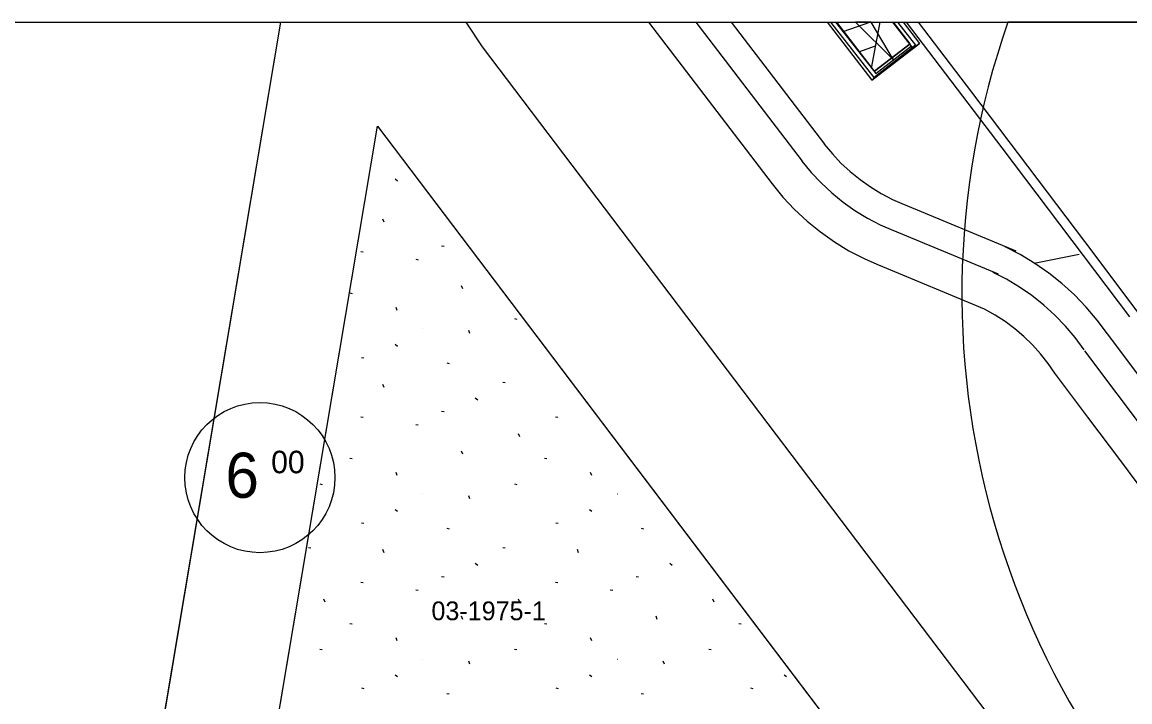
# Model space of a CAD drawing. Extents: x 413946 to 415528, y 4453939 to 4454944.
# Drawn here: x 414350.4 to 414409.5, y 4454907.7 to 4454944 of the extents above; entities that cross this region are included whole.
import ezdxf

# ---------------------------------------------------------------- set-up
doc = ezdxf.new("R2010")
doc.units = 0
for name, color, linetype in [('0_KADASTRO', 7, 'Continuous'), ('0_ÇERÇEVE', 7, 'Continuous'), ('Level 28', 7, 'Continuous'), ('Level 29', 7, 'Continuous'), ('Level 34', 7, 'Continuous'), ('Level 41', 7, 'Continuous'), ('Level 53', 7, 'Continuous'), ('Level 58', 7, 'Continuous'), ('Level 62', 7, 'Continuous'), ('SEMBOL', 7, 'Continuous')]:
    doc.layers.add(name, color=color, linetype=linetype)

msp = doc.modelspace()

# ---------------------------------------------------------------- linework, layer by layer
at = {"layer": '0_KADASTRO'}
for points in [[(414364.196, 4454943.957), (414356.8, 4454900.03), (414337.07, 4454903.37), (414329.44, 4454904.67), (414313.82, 4454907.32), (414291.88, 4454911.04), (414297.69, 4454930.45), (414299.05, 4454935), (414301.17, 4454942.09), (414301.729, 4454943.957)], [(414301.729, 4454943.957), (414364.196, 4454943.957)]]:
    msp.add_lwpolyline(points, dxfattribs=at)
msp.add_lwpolyline([(414362.46, 4454897.43), (414369.36, 4454938.42), (414392.9, 4454907.35), (414404.99, 4454891.41)], close=True, dxfattribs=at)
at = {"layer": '0_ÇERÇEVE'}
msp.add_lwpolyline([(413945.566, 4454943.957), (415494.137, 4454943.957), (415494.137, 4453939.478), (413945.566, 4453939.478)], close=True, dxfattribs=at)
at = {"layer": 'Level 28'}
for p, q in [((414364.196, 4454943.957), (414356.8, 4454900.03)), ((414362.46, 4454897.43), (414369.36, 4454938.42))]:
    msp.add_line(p, q, dxfattribs=at)
at = {"layer": 'Level 29'}
msp.add_line((414369.36, 4454938.42), (414399.16, 4454899.097), dxfattribs=at)
at = {"layer": 'Level 34'}
for points in [[(414364.196, 4454943.957), (414356.8, 4454900.03), (414329.44, 4454904.67), (414313.82, 4454907.32), (414291.88, 4454911.04), (414297.69, 4454930.45), (414301.17, 4454942.09), (414301.729, 4454943.957)], [(414301.729, 4454943.957), (414364.196, 4454943.957)]]:
    msp.add_lwpolyline(points, dxfattribs=at)
at = {"layer": 'Level 41'}
for p, q in [((414370.296, 4454935.605), (414370.423, 4454935.506)), ((414370.296, 4454935.605), (414370.423, 4454935.506)), ((414369.715, 4454933.302), (414369.65, 4454933.464)), ((414369.715, 4454933.302), (414369.65, 4454933.464)), ((414368.475, 4454931.734), (414368.601, 4454931.711)), ((414368.475, 4454931.734), (414368.601, 4454931.711)), ((414372.78, 4454932.038), (414372.906, 4454932.015)), ((414372.78, 4454932.038), (414372.906, 4454932.015)), ((414371.404, 4454931.324), (414371.531, 4454931.3)), ((414371.404, 4454931.324), (414371.531, 4454931.3)), ((414373.909, 4454929.75), (414373.844, 4454929.914)), ((414373.909, 4454929.75), (414373.844, 4454929.914)), ((414367.891, 4454929.53), (414368.017, 4454929.506)), ((414367.891, 4454929.53), (414368.017, 4454929.506)), ((414370.413, 4454928.601), (414370.349, 4454928.762)), ((414370.413, 4454928.601), (414370.349, 4454928.762)), ((414376.655, 4454928.162), (414376.781, 4454928.138)), ((414376.655, 4454928.162), (414376.781, 4454928.138)), ((414371.771, 4454927.637), (414371.779, 4454927.636)), ((414371.771, 4454927.637), (414371.779, 4454927.636)), ((414374.29, 4454927.368), (414374.225, 4454927.53)), ((414374.29, 4454927.368), (414374.225, 4454927.53)), ((414370.296, 4454926.799), (414370.423, 4454926.7)), ((414370.296, 4454926.799), (414370.423, 4454926.7)), ((414368.502, 4454926.094), (414368.628, 4454926.069)), ((414368.502, 4454926.094), (414368.628, 4454926.069)), ((414373.05, 4454925.8), (414373.177, 4454925.776)), ((414373.05, 4454925.8), (414373.177, 4454925.776)), ((414369.715, 4454924.496), (414369.65, 4454924.658)), ((414369.715, 4454924.496), (414369.65, 4454924.658)), ((414376.05, 4454924.776), (414376.175, 4454924.751)), ((414376.05, 4454924.776), (414376.175, 4454924.751)), ((414374.575, 4454923.938), (414374.702, 4454923.838)), ((414374.575, 4454923.938), (414374.702, 4454923.838)), ((414368.475, 4454922.928), (414368.601, 4454922.905)), ((414368.475, 4454922.928), (414368.601, 4454922.905)), ((414372.78, 4454923.232), (414372.906, 4454923.209)), ((414372.78, 4454923.232), (414372.906, 4454923.209)), ((414378.843, 4454922.928), (414378.969, 4454922.905)), ((414378.843, 4454922.928), (414378.969, 4454922.905)), ((414371.404, 4454922.518), (414371.531, 4454922.494)), ((414371.404, 4454922.518), (414371.531, 4454922.494)), ((414376.94, 4454921.859), (414376.874, 4454922.021)), ((414376.94, 4454921.859), (414376.874, 4454922.021)), ((414373.909, 4454920.944), (414373.844, 4454921.108)), ((414373.909, 4454920.944), (414373.844, 4454921.108)), ((414367.891, 4454920.724), (414368.017, 4454920.7)), ((414367.891, 4454920.724), (414368.017, 4454920.7)), ((414378.259, 4454920.724), (414378.385, 4454920.7)), ((414378.259, 4454920.724), (414378.385, 4454920.7)), ((414370.413, 4454919.795), (414370.349, 4454919.956)), ((414370.413, 4454919.795), (414370.349, 4454919.956)), ((414380.781, 4454919.795), (414380.717, 4454919.956)), ((414380.781, 4454919.795), (414380.717, 4454919.956)), ((414366.287, 4454919.356), (414366.413, 4454919.332)), ((414366.287, 4454919.356), (414366.413, 4454919.332)), ((414376.655, 4454919.356), (414376.781, 4454919.332)), ((414376.655, 4454919.356), (414376.781, 4454919.332)), ((414371.771, 4454918.831), (414371.779, 4454918.83)), ((414371.771, 4454918.831), (414371.779, 4454918.83)), ((414374.29, 4454918.562), (414374.225, 4454918.724)), ((414374.29, 4454918.562), (414374.225, 4454918.724)), ((414382.139, 4454918.831), (414382.147, 4454918.83)), ((414382.139, 4454918.831), (414382.147, 4454918.83)), ((414370.296, 4454917.993), (414370.423, 4454917.894)), ((414370.296, 4454917.993), (414370.423, 4454917.894)), ((414380.664, 4454917.993), (414380.791, 4454917.894)), ((414380.664, 4454917.993), (414380.791, 4454917.894)), ((414368.502, 4454917.288), (414368.628, 4454917.263)), ((414368.502, 4454917.288), (414368.628, 4454917.263)), ((414373.05, 4454916.994), (414373.177, 4454916.97)), ((414373.05, 4454916.994), (414373.177, 4454916.97)), ((414378.87, 4454917.288), (414378.996, 4454917.263)), ((414378.87, 4454917.288), (414378.996, 4454917.263)), ((414383.418, 4454916.994), (414383.545, 4454916.97)), ((414383.418, 4454916.994), (414383.545, 4454916.97)), ((414365.682, 4454915.97), (414365.807, 4454915.945)), ((414365.682, 4454915.97), (414365.807, 4454915.945)), ((414369.715, 4454915.69), (414369.65, 4454915.852)), ((414369.715, 4454915.69), (414369.65, 4454915.852)), ((414376.05, 4454915.97), (414376.175, 4454915.945)), ((414376.05, 4454915.97), (414376.175, 4454915.945)), ((414380.083, 4454915.69), (414380.018, 4454915.852)), ((414380.083, 4454915.69), (414380.018, 4454915.852)), ((414374.575, 4454915.132), (414374.702, 4454915.032)), ((414374.575, 4454915.132), (414374.702, 4454915.032)), ((414384.943, 4454915.132), (414385.07, 4454915.032)), ((414384.943, 4454915.132), (414385.07, 4454915.032)), ((414372.78, 4454914.426), (414372.906, 4454914.403)), ((414372.78, 4454914.426), (414372.906, 4454914.403)), ((414383.148, 4454914.426), (414383.274, 4454914.403)), ((414383.148, 4454914.426), (414383.274, 4454914.403)), ((414368.475, 4454914.122), (414368.601, 4454914.099)), ((414368.475, 4454914.122), (414368.601, 4454914.099)), ((414378.843, 4454914.122), (414378.969, 4454914.099)), ((414378.843, 4454914.122), (414378.969, 4454914.099)), ((414371.404, 4454913.712), (414371.531, 4454913.688)), ((414371.404, 4454913.712), (414371.531, 4454913.688)), ((414381.772, 4454913.712), (414381.899, 4454913.688)), ((414381.772, 4454913.712), (414381.899, 4454913.688)), ((414366.572, 4454913.053), (414366.506, 4454913.215)), ((414366.572, 4454913.053), (414366.506, 4454913.215)), ((414376.94, 4454913.053), (414376.874, 4454913.215)), ((414376.94, 4454913.053), (414376.874, 4454913.215)), ((414387.308, 4454913.053), (414387.242, 4454913.215)), ((414387.308, 4454913.053), (414387.242, 4454913.215)), ((414373.909, 4454912.138), (414373.844, 4454912.302)), ((414373.909, 4454912.138), (414373.844, 4454912.302)), ((414384.277, 4454912.138), (414384.212, 4454912.302)), ((414384.277, 4454912.138), (414384.212, 4454912.302)), ((414367.891, 4454911.918), (414368.017, 4454911.894)), ((414367.891, 4454911.918), (414368.017, 4454911.894)), ((414378.259, 4454911.918), (414378.385, 4454911.894)), ((414378.259, 4454911.918), (414378.385, 4454911.894)), ((414388.627, 4454911.918), (414388.753, 4454911.894)), ((414388.627, 4454911.918), (414388.753, 4454911.894)), ((414370.413, 4454910.989), (414370.349, 4454911.15)), ((414370.413, 4454910.989), (414370.349, 4454911.15)), ((414380.781, 4454910.989), (414380.717, 4454911.15)), ((414380.781, 4454910.989), (414380.717, 4454911.15)), ((414366.287, 4454910.55), (414366.413, 4454910.526)), ((414366.287, 4454910.55), (414366.413, 4454910.526)), ((414376.655, 4454910.55), (414376.781, 4454910.526)), ((414376.655, 4454910.55), (414376.781, 4454910.526)), ((414387.023, 4454910.55), (414387.149, 4454910.526)), ((414387.023, 4454910.55), (414387.149, 4454910.526)), ((414371.771, 4454910.025), (414371.779, 4454910.024)), ((414371.771, 4454910.025), (414371.779, 4454910.024)), ((414374.29, 4454909.756), (414374.225, 4454909.918)), ((414374.29, 4454909.756), (414374.225, 4454909.918)), ((414382.139, 4454910.025), (414382.147, 4454910.024)), ((414382.139, 4454910.025), (414382.147, 4454910.024)), ((414384.658, 4454909.756), (414384.593, 4454909.918)), ((414384.658, 4454909.756), (414384.593, 4454909.918)), ((414370.296, 4454909.187), (414370.423, 4454909.088)), ((414370.296, 4454909.187), (414370.423, 4454909.088)), ((414380.664, 4454909.187), (414380.791, 4454909.088)), ((414380.664, 4454909.187), (414380.791, 4454909.088)), ((414391.032, 4454909.187), (414391.159, 4454909.088)), ((414391.032, 4454909.187), (414391.159, 4454909.088)), ((414368.502, 4454908.482), (414368.628, 4454908.457)), ((414368.502, 4454908.482), (414368.628, 4454908.457)), ((414373.05, 4454908.188), (414373.177, 4454908.164)), ((414373.05, 4454908.188), (414373.177, 4454908.164)), ((414378.87, 4454908.482), (414378.996, 4454908.457)), ((414378.87, 4454908.482), (414378.996, 4454908.457)), ((414383.418, 4454908.188), (414383.545, 4454908.164)), ((414383.418, 4454908.188), (414383.545, 4454908.164)), ((414389.238, 4454908.482), (414389.364, 4454908.457)), ((414389.238, 4454908.482), (414389.364, 4454908.457))]:
    msp.add_line(p, q, dxfattribs=at)
at = {"layer": 'Level 53'}
for p, q in [((414393.779, 4454943.957), (414395.927, 4454941.218)), ((414394.175, 4454943.452), (414395.599, 4454943.957)), ((414394.841, 4454943.957), (414396.873, 4454941.957)), ((414396.873, 4454941.957), (414395.681, 4454943.957)), ((414397.876, 4454942.613), (414396.822, 4454943.957)), ((414395.022, 4454942.373), (414395.913, 4454942.689)), ((414395.927, 4454941.218), (414397.819, 4454942.694))]:
    msp.add_line(p, q, dxfattribs=at)
for points in [[(414393.521, 4454943.957), (414397.083, 4454943.957)], [(414397.083, 4454943.957), (414398.04, 4454942.738), (414395.83, 4454941.012), (414393.521, 4454943.957)], [(414395.681, 4454943.957), (414394.841, 4454943.957)], [(414395.695, 4454941.514), (414396.147, 4454943.957)]]:
    msp.add_lwpolyline(points, dxfattribs=at)
at = {"layer": 'Level 58'}
msp.add_lwpolyline([(414486.152, 4454943.957), (414402.962, 4454943.957)], dxfattribs=at)
msp.add_arc((414444.557, 4454929.473), 44.045, 160.80118, 19.19882, dxfattribs=at)
at = {"layer": 'Level 62'}
for p, q in [((414374.078, 4454943.957), (414374.939, 4454942.648)), ((414383.815, 4454943.957), (414390.402, 4454935.339)), ((414386.331, 4454943.957), (414391.99, 4454936.553)), ((414388.219, 4454943.957), (414393.182, 4454937.465)), ((414393.334, 4454943.957), (414395.717, 4454940.863)), ((414395.851, 4454941.344), (414393.839, 4454943.957)), ((414397.753, 4454942.809), (414396.869, 4454943.957)), ((414397.373, 4454943.957), (414398.252, 4454942.816)), ((414395.717, 4454940.863), (414398.252, 4454942.815)), ((414397.753, 4454942.809), (414395.851, 4454941.344)), ((414395.851, 4454941.344), (414397.752, 4454942.809)), ((414397.935, 4454942.571), (414398.252, 4454942.816)), ((414397.935, 4454942.571), (414398.252, 4454942.816)), ((414398.253, 4454942.816), (414397.936, 4454942.572)), ((414397.936, 4454942.572), (414395.717, 4454940.863)), ((414395.717, 4454940.863), (414396.034, 4454941.107)), ((414395.717, 4454940.863), (414396.034, 4454941.107)), ((414403.406, 4454931.756), (414397.424, 4454934.242)), ((414402.458, 4454930.522), (414396.848, 4454932.857)), ((414404.363, 4454931.11), (414406.755, 4454931.588)), ((414401.721, 4454928.663), (414396.08, 4454931.011))]:
    msp.add_line(p, q, dxfattribs=at)
for points in [[(414409.464, 4454928.259), (414402.661, 4454937.257), (414397.565, 4454943.957)], [(414407.563, 4454931.613), (414401.043, 4454940.227), (414398.204, 4454943.957)], [(414374.939, 4454942.648), (414406.666, 4454900.782), (414404.4, 4454889.986)], [(414393.178, 4454937.465), (414393.606, 4454936.943), (414394.067, 4454936.452), (414394.56, 4454935.992), (414395.084, 4454935.567), (414395.635, 4454935.178), (414396.21, 4454934.828), (414396.808, 4454934.516), (414397.426, 4454934.246)], [(414391.987, 4454936.554), (414392.478, 4454935.954), (414393.008, 4454935.389), (414393.576, 4454934.861), (414394.178, 4454934.372), (414394.811, 4454933.925), (414395.473, 4454933.521), (414396.161, 4454933.163), (414396.871, 4454932.852)], [(414390.397, 4454935.34), (414390.974, 4454934.636), (414391.597, 4454933.972), (414392.263, 4454933.352), (414392.97, 4454932.778), (414393.713, 4454932.253), (414394.491, 4454931.779), (414395.298, 4454931.359), (414396.132, 4454930.994)], [(414408.267, 4454927.355), (414407.728, 4454928.081), (414407.144, 4454928.771), (414406.515, 4454929.42), (414405.845, 4454930.028), (414405.137, 4454930.59), (414404.393, 4454931.104), (414403.618, 4454931.569), (414402.814, 4454931.982)], [(414423.619, 4454910.184), (414421.619, 4454912.868), (414419.618, 4454915.551), (414417.614, 4454918.232), (414415.608, 4454920.911), (414413.6, 4454923.589), (414411.59, 4454926.265), (414409.577, 4454928.94), (414407.563, 4454931.613)], [(414407.034, 4454926.501), (414406.553, 4454927.149), (414406.032, 4454927.763), (414405.472, 4454928.343), (414404.874, 4454928.884), (414404.243, 4454929.385), (414403.581, 4454929.844), (414402.889, 4454930.258), (414402.172, 4454930.626)], [(414405.47, 4454925.251), (414405.106, 4454925.778), (414404.708, 4454926.281), (414404.278, 4454926.756), (414403.819, 4454927.202), (414403.331, 4454927.618), (414402.817, 4454928.001), (414402.28, 4454928.35), (414401.721, 4454928.663)], [(414422.015, 4454908.99), (414420.302, 4454911.289), (414418.587, 4454913.588), (414416.871, 4454915.885), (414415.153, 4454918.182), (414413.434, 4454920.477), (414411.713, 4454922.771), (414409.991, 4454925.064), (414408.267, 4454927.355)], [(414420.812, 4454908.094), (414419.099, 4454910.393), (414417.385, 4454912.691), (414415.669, 4454914.987), (414413.952, 4454917.283), (414412.233, 4454919.577), (414410.513, 4454921.87), (414408.792, 4454924.162), (414407.068, 4454926.453)], [(414419.471, 4454906.546), (414417.726, 4454908.888), (414415.98, 4454911.229), (414414.232, 4454913.569), (414412.483, 4454915.908), (414410.732, 4454918.246), (414408.98, 4454920.582), (414407.225, 4454922.917), (414405.47, 4454925.251)]]:
    msp.add_lwpolyline(points, dxfattribs=at)
at = {"layer": 'SEMBOL'}
msp.add_circle((414363.093, 4454919.689), 4, dxfattribs=at)

# ---------------------------------------------------------------- texts
at = {"layer": '0_KADASTRO'}
msp.add_text('03-1975-1', height=1, dxfattribs=at).set_placement((414372.237, 4454912.092))
at = {"layer": 'SEMBOL'}
for s, height, p in [('6', 2.4, (414361.257, 4454918.617)), ('00', 1.2, (414363.693, 4454919.922))]:
    msp.add_text(s, height=height, dxfattribs=at).set_placement(p)

doc.saveas('drawing.dxf')
